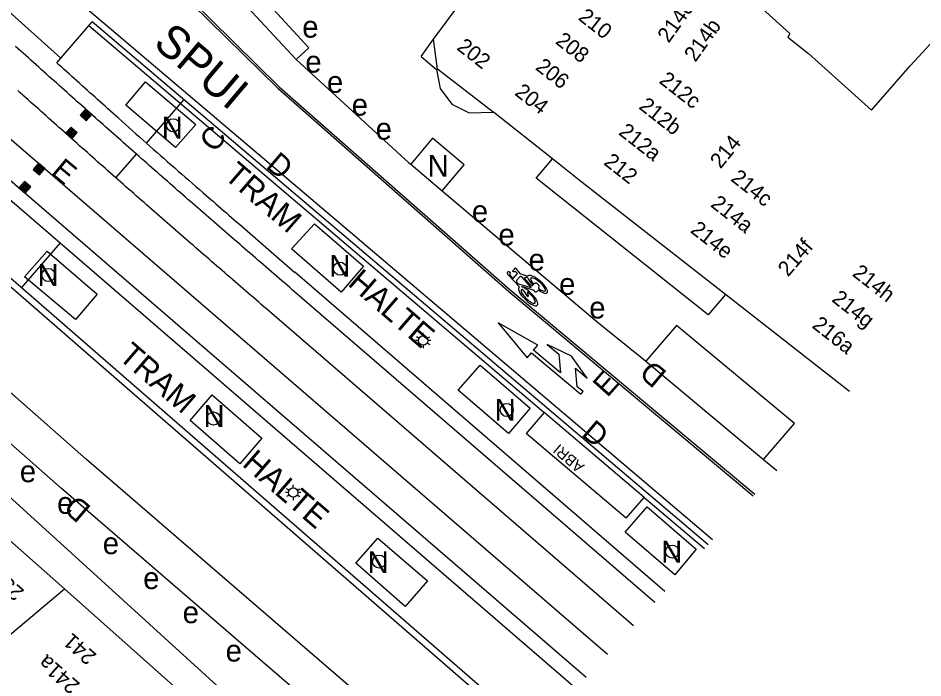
# Model space of a CAD drawing. Extents: x 81617 to 82144, y 454649 to 455150.
# Drawn here: x 81733.29 to 81774.65, y 454680 to 454710.19 of the extents above; entities that cross this region are included whole.
import ezdxf

# ---------------------------------------------------------------- set-up
doc = ezdxf.new("R2010")
doc.units = 0
doc.layers.add('B-WE-OG-TOPOGRAFIE-G', color=7, linetype='Continuous')
doc.layers.add('B-WE-VW-MARKERING-G', color=7, linetype='Continuous')

msp = doc.modelspace()

# ---------------------------------------------------------------- linework, layer by layer
at = {"layer": 'B-WE-OG-TOPOGRAFIE-G'}
for p, q in [((81741.689, 454712.958), (81745.997, 454708.287)), ((81735.247, 454708.351), (81732.548, 454710.771)), ((81735.061, 454708.136), (81736.68, 454710.01)), ((81751.713, 454708.435), (81752.28, 454709.218)), ((81751.713, 454708.435), (81752.411, 454707.829)), ((81735.168, 454708.039), (81735.061, 454708.136)), ((81735.286, 454707.933), (81735.168, 454708.039)), ((81735.403, 454707.827), (81735.286, 454707.933)), ((81735.52, 454707.722), (81735.403, 454707.827)), ((81735.637, 454707.616), (81735.52, 454707.722)), ((81735.754, 454707.511), (81735.637, 454707.616)), ((81735.872, 454707.405), (81735.754, 454707.511)), ((81752.411, 454707.829), (81752.586, 454706.961)), ((81735.989, 454707.3), (81735.872, 454707.405)), ((81736.106, 454707.195), (81735.989, 454707.3)), ((81736.223, 454707.089), (81736.106, 454707.195)), ((81736.341, 454706.984), (81736.223, 454707.089)), ((81736.458, 454706.878), (81736.341, 454706.984)), ((81736.575, 454706.773), (81736.458, 454706.878)), ((81736.692, 454706.668), (81736.575, 454706.773)), ((81736.81, 454706.563), (81736.692, 454706.668)), ((81752.586, 454706.961), (81753.121, 454706.255)), ((81736.927, 454706.457), (81736.81, 454706.563)), ((81737.044, 454706.352), (81736.927, 454706.457)), ((81737.162, 454706.247), (81737.044, 454706.352)), ((81737.279, 454706.142), (81737.162, 454706.247)), ((81739.158, 454704.466), (81740.872, 454706.45)), ((81753.121, 454706.255), (81753.909, 454705.852)), ((81737.397, 454706.037), (81737.279, 454706.142)), ((81737.514, 454705.932), (81737.397, 454706.037)), ((81737.631, 454705.827), (81737.514, 454705.932)), ((81737.749, 454705.722), (81737.631, 454705.827)), ((81753.909, 454705.852), (81755.005, 454705.881)), ((81737.866, 454705.616), (81737.749, 454705.722)), ((81731.051, 454703.494), (81735.213, 454699.899)), ((81751.235, 454703.498), (81752.673, 454702.282)), ((81735.213, 454699.899), (81733.45, 454697.857)), ((81735.213, 454699.899), (81742.024, 454694.015)), ((81762.856, 454683.95), (81745.946, 454698.556)), ((81751.589, 454695.435), (81751.448, 454695.435)), ((81751.628, 454695.535), (81751.498, 454695.61)), ((81751.801, 454695.635), (81751.801, 454695.785)), ((81751.974, 454695.535), (81752.104, 454695.61)), ((81752.154, 454695.435), (81752.013, 454695.435)), ((81751.628, 454695.335), (81751.498, 454695.26)), ((81751.801, 454695.235), (81751.801, 454695.085)), ((81751.974, 454695.335), (81752.104, 454695.26)), ((81761.987, 454694.49), (81767.365, 454689.988)), ((81742.024, 454694.015), (81758.788, 454679.535)), ((81761.09, 454687.306), (81756.517, 454691.19)), ((81730.968, 454690.035), (81736.067, 454685.401)), ((81767.365, 454689.988), (81767.964, 454689.493)), ((81745.868, 454688.683), (81745.868, 454688.833)), ((81745.656, 454688.483), (81745.515, 454688.483)), ((81745.695, 454688.583), (81745.565, 454688.658)), ((81746.041, 454688.583), (81746.171, 454688.658)), ((81746.221, 454688.483), (81746.08, 454688.483)), ((81745.695, 454688.383), (81745.565, 454688.308)), ((81745.868, 454688.283), (81745.868, 454688.133)), ((81746.041, 454688.383), (81746.171, 454688.308)), ((81736.067, 454685.401), (81751.371, 454671.486))]:
    msp.add_line(p, q, dxfattribs=at)
for points in [[(81792.953, 454739.866), (81790.902, 454737.492), (81786.471, 454732.664), (81770.094, 454714.466), (81766.995, 454710.894), (81768.568, 454709.482), (81768.466, 454709.313), (81769.411, 454708.558), (81772.299, 454705.967), (81774.071, 454708.001), (81775.156, 454709.186), (81775.527, 454708.939), (81779.184, 454712.926), (81782.472, 454716.506), (81785.115, 454719.385), (81785.644, 454719.976)], [(81711.061, 454723.559), (81760.224, 454681.093)], [(81710.123, 454722.473), (81759.251, 454680.037)], [(81757.71, 454703.742), (81755.014, 454705.875), (81755.005, 454705.881), (81752.456, 454707.845), (81752.28, 454709.218), (81755.661, 454713.78), (81758.563, 454717.431)], [(81735.873, 454716.274), (81745.231, 454707.045), (81755.786, 454697.754), (81766.958, 454688.402)], [(81741.689, 454712.958), (81742.277, 454713.5), (81746.585, 454708.829), (81745.997, 454708.287)], [(81765.034, 454686.313), (81763.503, 454687.615), (81746.559, 454702.015), (81735.955, 454711.019)], [(81764.83, 454686.092), (81763.309, 454687.386), (81746.365, 454701.786), (81736.68, 454710.01)], [(81757.326, 454692.143), (81736.52, 454709.825)], [(81762.393, 454683.448), (81745.824, 454697.76), (81745.824, 454697.76), (81745.704, 454697.864), (81745.585, 454697.967), (81745.465, 454698.07), (81745.346, 454698.173), (81745.226, 454698.276), (81745.107, 454698.38), (81744.987, 454698.483), (81744.868, 454698.586), (81744.748, 454698.689), (81744.629, 454698.792), (81744.51, 454698.896), (81744.39, 454698.999), (81744.271, 454699.102), (81744.151, 454699.205), (81744.032, 454699.309), (81743.913, 454699.412), (81743.793, 454699.515), (81743.674, 454699.618), (81743.555, 454699.722), (81743.435, 454699.825), (81743.316, 454699.928), (81743.197, 454700.032), (81743.078, 454700.135), (81742.959, 454700.238), (81742.839, 454700.342), (81742.72, 454700.445), (81742.601, 454700.549), (81742.482, 454700.652), (81742.363, 454700.755), (81742.244, 454700.859), (81742.125, 454700.962), (81742.006, 454701.066), (81741.887, 454701.169), (81741.768, 454701.273), (81741.649, 454701.377), (81741.53, 454701.48), (81741.411, 454701.584), (81741.292, 454701.688), (81741.292, 454701.688), (81741.174, 454701.791), (81741.056, 454701.894), (81740.938, 454701.997), (81740.82, 454702.1), (81740.702, 454702.203), (81740.584, 454702.306), (81740.466, 454702.409), (81740.349, 454702.513), (81740.231, 454702.616), (81740.113, 454702.719), (81739.995, 454702.823), (81739.877, 454702.926), (81739.76, 454703.029), (81739.642, 454703.133), (81739.524, 454703.236), (81739.407, 454703.34), (81739.289, 454703.443), (81739.172, 454703.547), (81739.054, 454703.65), (81738.936, 454703.754), (81738.819, 454703.858), (81738.702, 454703.961), (81738.584, 454704.065), (81738.467, 454704.169), (81738.349, 454704.272), (81738.232, 454704.376), (81738.115, 454704.48), (81737.997, 454704.584), (81737.88, 454704.688), (81737.763, 454704.792), (81737.645, 454704.896), (81737.528, 454705), (81737.411, 454705.104), (81737.411, 454705.104), (81737.293, 454705.208), (81737.175, 454705.313), (81737.057, 454705.418), (81736.939, 454705.523), (81736.822, 454705.628), (81736.704, 454705.733), (81736.586, 454705.838), (81736.468, 454705.942), (81736.351, 454706.047), (81736.233, 454706.152), (81736.115, 454706.257), (81735.997, 454706.362), (81735.88, 454706.468), (81735.762, 454706.573), (81735.644, 454706.678), (81735.527, 454706.783), (81735.409, 454706.888), (81735.291, 454706.993), (81735.174, 454707.098), (81735.056, 454707.204), (81734.939, 454707.309), (81734.821, 454707.414), (81734.703, 454707.519), (81734.586, 454707.625), (81734.468, 454707.73), (81734.351, 454707.835), (81734.233, 454707.941), (81734.116, 454708.046), (81733.998, 454708.151), (81733.881, 454708.257), (81733.763, 454708.362), (81733.646, 454708.467), (81733.528, 454708.573), (81733.41, 454708.678), (81733.293, 454708.784), (81733.175, 454708.889)], [(81745.997, 454708.287), (81751.138, 454703.58), (81751.235, 454703.498)], [(81740.493, 454704.265), (81738.215, 454706.201), (81739.122, 454707.268), (81741.408, 454705.325), (81740.493, 454704.265)], [(81761.42, 454682.392), (81744.886, 454696.674), (81744.885, 454696.674), (81744.766, 454696.778), (81744.647, 454696.881), (81744.527, 454696.984), (81744.408, 454697.087), (81744.288, 454697.19), (81744.169, 454697.294), (81744.049, 454697.397), (81743.93, 454697.5), (81743.81, 454697.603), (81743.691, 454697.707), (81743.571, 454697.81), (81743.452, 454697.913), (81743.332, 454698.017), (81743.213, 454698.12), (81743.093, 454698.223), (81742.974, 454698.327), (81742.854, 454698.43), (81742.735, 454698.533), (81742.615, 454698.637), (81742.496, 454698.74), (81742.377, 454698.844), (81742.257, 454698.947), (81742.138, 454699.051), (81742.018, 454699.154), (81741.899, 454699.258), (81741.78, 454699.361), (81741.66, 454699.465), (81741.541, 454699.569), (81741.422, 454699.672), (81741.302, 454699.776), (81741.183, 454699.88), (81741.064, 454699.983), (81740.945, 454700.087), (81740.825, 454700.191), (81740.706, 454700.295), (81740.587, 454700.399), (81740.468, 454700.502), (81740.349, 454700.606), (81740.349, 454700.606), (81740.23, 454700.71), (81740.112, 454700.813), (81739.994, 454700.916), (81739.876, 454701.02), (81739.757, 454701.123), (81739.639, 454701.226), (81739.521, 454701.33), (81739.403, 454701.433), (81739.285, 454701.537), (81739.167, 454701.64), (81739.049, 454701.744), (81738.931, 454701.848), (81738.813, 454701.951), (81738.695, 454702.055), (81738.577, 454702.159), (81738.459, 454702.262), (81738.341, 454702.366), (81738.223, 454702.47), (81738.105, 454702.574), (81737.987, 454702.678), (81737.87, 454702.782), (81737.752, 454702.885), (81737.634, 454702.989), (81737.516, 454703.093), (81737.399, 454703.197), (81737.281, 454703.301), (81737.163, 454703.406), (81737.046, 454703.51), (81736.928, 454703.614), (81736.811, 454703.718), (81736.693, 454703.822), (81736.576, 454703.926), (81736.458, 454704.031), (81736.458, 454704.031), (81736.34, 454704.136), (81736.222, 454704.241), (81736.104, 454704.346), (81735.986, 454704.451), (81735.868, 454704.556), (81735.75, 454704.661), (81735.632, 454704.766), (81735.514, 454704.871), (81735.396, 454704.976), (81735.278, 454705.082), (81735.16, 454705.187), (81735.042, 454705.292), (81734.924, 454705.397), (81734.806, 454705.502), (81734.688, 454705.608), (81734.57, 454705.713), (81734.453, 454705.818), (81734.335, 454705.924), (81734.217, 454706.029), (81734.099, 454706.134), (81733.982, 454706.24), (81733.864, 454706.345), (81733.746, 454706.45), (81733.629, 454706.556), (81733.511, 454706.661), (81733.393, 454706.767), (81733.276, 454706.872)], [(81752.673, 454702.282), (81753.682, 454703.476), (81752.24, 454704.688), (81751.235, 454703.498)], [(81765.619, 454697.539), (81764.838, 454696.614), (81756.972, 454702.861), (81757.71, 454703.742)], [(81765.619, 454697.539), (81758.935, 454702.773), (81758.02, 454703.496), (81757.71, 454703.742)], [(81727.987, 454702.211), (81739.09, 454692.554), (81752.463, 454680.921), (81755.021, 454678.695)], [(81741.741, 454702.202), (81741.86, 454702.098), (81741.978, 454701.995), (81742.097, 454701.891), (81742.216, 454701.788), (81742.335, 454701.684), (81742.454, 454701.581), (81742.573, 454701.477), (81742.692, 454701.374), (81742.811, 454701.271), (81742.93, 454701.167), (81743.049, 454701.064), (81743.168, 454700.961), (81743.287, 454700.857), (81743.406, 454700.754), (81745.944, 454698.553)], [(81752.673, 454702.282), (81759.659, 454696.38), (81760.152, 454695.978), (81761.803, 454694.638), (81761.987, 454694.49)], [(81729.3, 454701.466), (81739.287, 454692.78), (81752.66, 454681.147), (81755.218, 454678.921)], [(81745.786, 454699.637), (81746.839, 454700.776), (81749.075, 454698.838), (81748.053, 454697.641), (81745.786, 454699.637)], [(81753.001, 454673.256), (81749.115, 454676.722), (81735.271, 454688.668), (81725.797, 454697.026), (81722.581, 454699.735)], [(81733.59, 454698.357), (81734.617, 454699.531), (81736.908, 454697.553), (81735.908, 454696.395), (81733.59, 454698.357)], [(81771.288, 454693.1), (81765.619, 454697.539)], [(81767.365, 454689.988), (81768.771, 454691.64), (81763.39, 454696.126), (81761.987, 454694.49)], [(81753.406, 454693.162), (81754.404, 454694.314), (81756.692, 454692.343), (81755.704, 454691.187), (81753.406, 454693.162)], [(81741.152, 454691.777), (81742.169, 454692.953), (81744.437, 454690.975), (81743.421, 454689.796), (81741.152, 454691.777)], [(81761.09, 454687.306), (81761.903, 454688.263), (81757.329, 454692.147), (81756.517, 454691.19)], [(81727.664, 454690.931), (81731.283, 454687.723), (81735.406, 454684.071), (81740.258, 454679.771), (81745.134, 454675.451), (81731.189, 454665.536), (81728.959, 454663.85), (81725.968, 454661.587)], [(81764.661, 454685.909), (81761.898, 454688.257)], [(81761.033, 454686.664), (81762.047, 454687.834), (81764.288, 454685.9), (81763.307, 454684.723), (81761.033, 454686.664)], [(81748.721, 454685.248), (81749.739, 454686.392), (81752.002, 454684.44), (81750.978, 454683.266), (81748.721, 454685.248)], [(81721.377, 454672.411), (81725.093, 454675.401), (81735.406, 454684.071)]]:
    msp.add_lwpolyline(points, dxfattribs=at)
for points in [[(81736.66, 454705.772), (81736.376, 454706.025), (81736.123, 454705.741), (81736.407, 454705.488)], [(81736.61, 454705.769), (81736.379, 454705.975), (81736.172, 454705.744), (81736.404, 454705.538)], [(81736.561, 454705.766), (81736.382, 454705.926), (81736.222, 454705.747), (81736.401, 454705.587)], [(81736.511, 454705.764), (81736.384, 454705.877), (81736.271, 454705.75), (81736.398, 454705.637)], [(81736.462, 454705.761), (81736.387, 454705.827), (81736.321, 454705.753), (81736.395, 454705.686)], [(81736.412, 454705.758), (81736.39, 454705.778), (81736.37, 454705.755), (81736.392, 454705.735)], [(81735.462, 454704.917), (81735.746, 454704.664), (81735.999, 454704.948), (81735.715, 454705.201)], [(81735.512, 454704.92), (81735.743, 454704.714), (81735.949, 454704.945), (81735.718, 454705.151)], [(81735.561, 454704.923), (81735.74, 454704.763), (81735.9, 454704.942), (81735.721, 454705.102)], [(81735.61, 454704.925), (81735.737, 454704.812), (81735.85, 454704.939), (81735.723, 454705.052)], [(81735.66, 454704.928), (81735.734, 454704.862), (81735.801, 454704.936), (81735.726, 454705.003)], [(81735.709, 454704.931), (81735.732, 454704.911), (81735.752, 454704.934), (81735.729, 454704.954)], [(81734.516, 454703.299), (81734.229, 454703.547), (81733.98, 454703.26), (81734.268, 454703.011)], [(81734.467, 454703.295), (81734.232, 454703.498), (81734.03, 454703.263), (81734.264, 454703.061)], [(81734.418, 454703.292), (81734.236, 454703.449), (81734.079, 454703.267), (81734.261, 454703.11)], [(81734.368, 454703.288), (81734.24, 454703.399), (81734.128, 454703.27), (81734.257, 454703.159)], [(81734.319, 454703.284), (81734.243, 454703.35), (81734.178, 454703.274), (81734.253, 454703.209)], [(81734.269, 454703.281), (81734.247, 454703.3), (81734.227, 454703.278), (81734.25, 454703.258)], [(81733.332, 454702.425), (81733.62, 454702.177), (81733.868, 454702.464), (81733.581, 454702.713)], [(81733.382, 454702.429), (81733.616, 454702.226), (81733.819, 454702.461), (81733.584, 454702.664)], [(81733.431, 454702.433), (81733.613, 454702.276), (81733.77, 454702.457), (81733.588, 454702.614)], [(81733.48, 454702.436), (81733.609, 454702.325), (81733.72, 454702.454), (81733.592, 454702.565)], [(81733.53, 454702.44), (81733.605, 454702.374), (81733.671, 454702.45), (81733.595, 454702.515)], [(81733.579, 454702.443), (81733.602, 454702.424), (81733.621, 454702.446), (81733.599, 454702.466)]]:
    msp.add_lwpolyline(points, close=True, dxfattribs=at)
for centre, radius in [((81740.379, 454705.281), 0.3), ((81748.005, 454698.724), 0.3), ((81734.679, 454698.432), 0.3), ((81751.801, 454695.435), 0.212), ((81755.626, 454692.258), 0.3), ((81742.228, 454691.87), 0.3), ((81745.868, 454688.483), 0.212), ((81763.183, 454685.782), 0.3), ((81749.794, 454685.324), 0.3)]:
    msp.add_circle(centre, radius, dxfattribs=at)
for centre, radius, start, end in [((82136.681, 455152.012), 598.6, 228.221989, 228.387614), ((82135.02, 455153.478), 598.597, 228.59978, 228.928494)]:
    msp.add_arc(centre, radius, start, end, dxfattribs=at)
at = {"layer": 'B-WE-VW-MARKERING-G'}
for p, q in [((81737.76, 454702.882), (81738.709, 454703.957)), ((81757.045, 454695.221), (81755.232, 454696.25)), ((81755.232, 454696.25), (81756.564, 454694.646)), ((81756.852, 454694.991), (81757.045, 454695.221)), ((81758.58, 454694.719), (81757.468, 454695.259)), ((81757.468, 454695.259), (81758.004, 454694.809)), ((81756.564, 454694.646), (81756.756, 454694.876)), ((81756.756, 454694.876), (81759.018, 454692.983)), ((81758.079, 454693.964), (81756.852, 454694.991)), ((81758.004, 454694.809), (81758.079, 454693.964)), ((81759.308, 454693.718), (81758.58, 454694.719)), ((81758.846, 454693.322), (81758.771, 454694.168)), ((81758.771, 454694.168), (81759.308, 454693.718)), ((81759.115, 454693.098), (81758.846, 454693.322)), ((81759.018, 454692.983), (81759.115, 454693.098))]:
    msp.add_line(p, q, dxfattribs=at)
for points in [[(81741.254, 454710.827), (81745.163, 454706.972), (81755.721, 454697.678), (81766.89, 454688.328)], [(81754.205, 454674.562), (81750.269, 454678.038), (81736.422, 454689.987), (81726.94, 454698.352), (81714.491, 454708.275)], [(81756.033, 454698.748), (81756.226, 454698.507)], [(81756.213, 454697.89), (81755.68, 454698.462)], [(81755.715, 454698.597), (81755.799, 454698.541)], [(81755.77, 454698.441), (81755.924, 454698.278), (81756.113, 454698.502), (81756.018, 454698.608)], [(81756.204, 454698.335), (81756.077, 454698.185)], [(81756.154, 454698.037), (81756.742, 454697.868), (81756.315, 454698.349)], [(81756.226, 454698.507), (81756.594, 454698.377)], [(81756.429, 454698.288), (81756.689, 454697.999)], [(81756.335, 454697.9), (81756.839, 454697.753)], [(81757.09, 454697.808), (81757.09, 454697.807)]]:
    msp.add_lwpolyline(points, dxfattribs=at)
for centre, major_axis, ratio, start_param, end_param in [((81755.866, 454698.462), (-0.0778, 0.0657), 0.951466, 6.106821, 7.217969), ((81756.271, 454698.273), (-0.0707, 0.0597), 0.951466, 4.868752, 6.235806), ((81757.041, 454698.01), (0.435, -0.383), 0.311979, 5.055467, 9.526588), ((81756.194, 454698.149), (-0.0951, 0.0803), 0.951466, 0.416101, 1.916869), ((81757.041, 454698.01), (0.435, -0.383), 0.311979, 3.55346, 4.48315), ((81757.055, 454697.998), (0.331, -0.284), 0.298624, 5.035956, 10.606751), ((81757.041, 454698.01), (0.435, -0.383), 0.311979, 4.48315, 4.485286), ((81757.055, 454697.998), (0.331, -0.284), 0.298624, 4.323566, 4.330384), ((81756.603, 454697.46), (0.419, -0.411), 0.337195, 2.965544, 8.864445), ((81756.604, 454697.461), (-0.315, 0.313), 0.305781, 6.11811, 11.365094), ((81756.301, 454697.748), (-0.0305, 0.0258), 0.951466, 4.515962, 5.19261), ((81755.844, 454697.181), (-0.615, 0.519), 0.951466, 4.25523, 4.724374), ((81756.576, 454697.657), (-0.00695, 0.00587), 0.951466, 5.132399, 7.244068), ((81756.993, 454697.674), (-0.334, 0.282), 0.951466, 0.769914, 1.166655), ((81756.588, 454697.482), (-0.0234, 0.0198), 0.951466, 0.933004, 4.202582)]:
    msp.add_ellipse(centre, major_axis=major_axis, ratio=ratio, start_param=start_param, end_param=end_param, dxfattribs=at)
for points in [[(81755.903, 454698.599), (81755.901, 454698.604), (81755.9, 454698.608), (81755.902, 454698.612), (81755.905, 454698.617), (81755.921, 454698.637), (81755.951, 454698.677), (81755.973, 454698.706), (81755.991, 454698.728), (81755.999, 454698.738), (81756.007, 454698.75), (81756.014, 454698.756), (81756.017, 454698.758), (81756.02, 454698.759), (81756.023, 454698.758), (81756.025, 454698.756), (81756.031, 454698.752), (81756.033, 454698.748), (81756.036, 454698.744)], [(81755.68, 454698.462), (81755.661, 454698.503), (81755.659, 454698.531), (81755.67, 454698.573), (81755.704, 454698.601), (81755.715, 454698.597)], [(81756.018, 454698.608), (81756.004, 454698.592), (81755.979, 454698.578), (81755.95, 454698.577), (81755.923, 454698.586), (81755.903, 454698.599)], [(81756.595, 454698.305), (81756.513, 454698.314), (81756.47, 454698.307), (81756.429, 454698.288)], [(81756.689, 454697.999), (81756.722, 454697.972), (81756.748, 454697.957), (81756.775, 454697.951), (81756.825, 454697.964)], [(81756.852, 454698.012), (81756.871, 454698.031), (81756.89, 454698.047), (81756.918, 454698.063), (81756.934, 454698.071), (81756.948, 454698.074), (81756.966, 454698.072), (81756.995, 454698.06), (81757.049, 454698.017), (81757.066, 454697.996), (81757.087, 454697.963), (81757.094, 454697.937), (81757.092, 454697.914), (81757.083, 454697.869), (81757.078, 454697.814)], [(81756.321, 454697.885), (81756.314, 454697.894), (81756.317, 454697.901), (81756.335, 454697.9)], [(81756.839, 454697.753), (81756.847, 454697.747), (81756.857, 454697.738), (81756.868, 454697.726), (81756.871, 454697.713), (81756.882, 454697.695), (81756.895, 454697.68), (81756.911, 454697.667), (81756.932, 454697.656), (81756.956, 454697.656), (81756.971, 454697.658), (81757.012, 454697.687), (81757.033, 454697.708), (81757.076, 454697.751)]]:
    msp.add_spline(points, degree=3, dxfattribs=at)

# ---------------------------------------------------------------- texts
at = {"layer": 'B-WE-OG-TOPOGRAFIE-G'}
for s, height, rotation, p in [('214d', 0.7, 54.4489, (81763.027, 454709.011)), ('210', 0.7, 321.935, (81758.851, 454710.143)), ('214b', 0.7, 54.4489, (81764.247, 454708.139)), ('SPUI', 1.5, 319.83, (81739.409, 454708.933)), ('208', 0.7, 321.935, (81757.808, 454709.054)), ('202', 0.7, 321.935, (81753.298, 454708.776)), ('206', 0.7, 321.935, (81756.897, 454707.863)), ('212c', 0.7, 321.8789, (81762.548, 454707.252)), ('204', 0.7, 321.935, (81755.946, 454706.702)), ('212b', 0.7, 321.8789, (81761.623, 454706.072)), ('C', 1, 49.7114, (81742.259, 454703.991)), ('212a', 0.7, 321.8789, (81760.697, 454704.892)), ('214', 0.7, 50.7046, (81765.397, 454703.259)), ('E', 1, 320.1265, (81734.743, 454703.073)), ('D', 1, 319.7491, (81744.571, 454703.367)), ('212', 0.7, 321.8789, (81760.018, 454703.518)), ('TRAM         HALTE', 1.05, 319.1284, (81742.655, 454702.893)), ('214c', 0.7, 321.9333, (81765.824, 454702.777)), ('214a', 0.7, 321.9333, (81764.901, 454701.596)), ('214e', 0.7, 321.9333, (81763.976, 454700.415)), ('214f', 0.7, 49.1872, (81768.482, 454698.32)), ('214h', 0.7, 321.9347, (81771.376, 454698.43)), ('214g', 0.7, 321.9347, (81770.438, 454697.259)), ('216a', 0.7, 321.9347, (81769.538, 454696.058)), ('TRAM         HALTE', 1.05, 319.1284, (81737.826, 454694.633)), ('D', 1, 139.9697, (81763, 454693.972)), ('E', 1, 48.1281, (81760.22, 454692.8)), ('D', 1, 319.6164, (81758.996, 454691.109)), ('ABRI', 0.5, 139.6625, (81759.21, 454689.727)), ('D', 1, 139.2364, (81736.682, 454687.797)), ('239c', 0.7, 138.4562, (81733.615, 454683.989)), ('241', 0.7, 138.4562, (81736.92, 454681.061)), ('241a', 0.7, 138.4562, (81736.159, 454679.73))]:
    msp.add_text(s, height=height, rotation=rotation, dxfattribs=at).set_placement(p)
for s, p in [('e', (81746.279, 454709.29)), ('e', (81746.419, 454707.692)), ('e', (81747.408, 454706.764)), ('e', (81748.54, 454705.723)), ('N', (81739.856, 454704.669)), ('e', (81749.633, 454704.624)), ('N', (81752.01, 454702.926)), ('e', (81754.032, 454700.851)), ('e', (81755.247, 454699.781)), ('N', (81747.517, 454698.35)), ('e', (81756.622, 454698.633)), ('N', (81734.179, 454697.932)), ('e', (81758.021, 454697.525)), ('e', (81759.397, 454696.443)), ('N', (81755.07, 454691.765)), ('N', (81741.767, 454691.48)), ('e', (81733.37, 454688.954)), ('e', (81735.074, 454687.508)), ('e', (81737.159, 454685.665)), ('N', (81762.683, 454685.282)), ('N', (81749.267, 454684.797)), ('e', (81739.009, 454684.068)), ('e', (81740.813, 454682.506)), ('e', (81742.776, 454680.751))]:
    msp.add_text(s, height=1, dxfattribs=at).set_placement(p)

doc.saveas('drawing.dxf')
